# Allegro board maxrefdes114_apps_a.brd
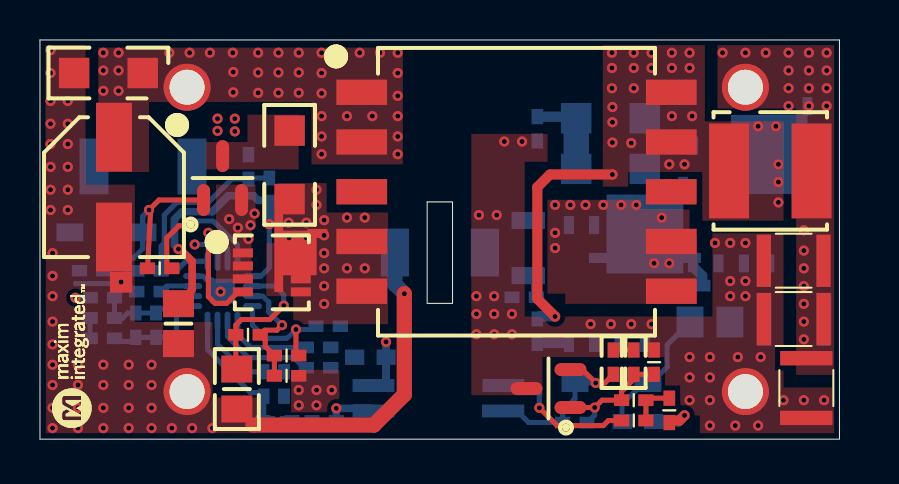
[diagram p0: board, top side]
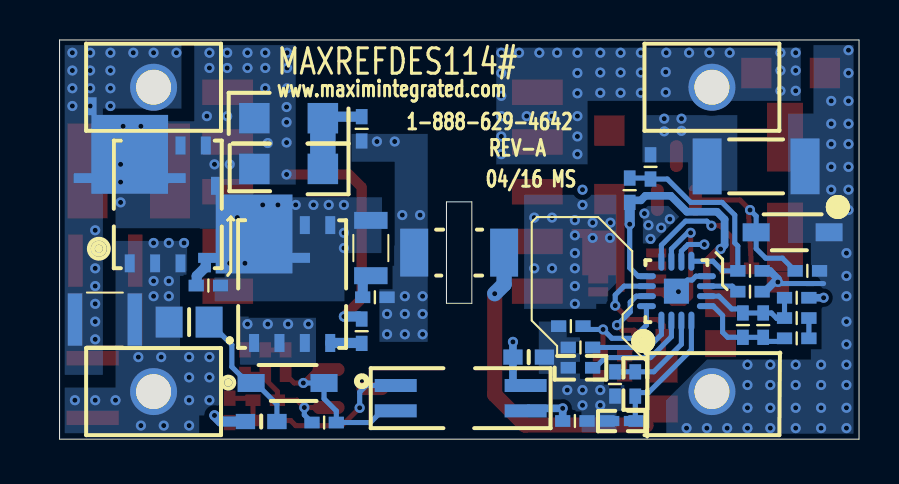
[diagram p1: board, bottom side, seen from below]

Outline 40 x 19.99 mm; copper layers: TOP, INTERNAL2, INTERNAL3, BOTTOM. Coordinates in mm from the lower left corner of the outline.
Outline path: 0,19.99 0,0 40,0 40,19.99 0,19.99 ; 19.38,11.88 19.38,6.8 20.65,6.8 20.65,11.88 19.38,11.88

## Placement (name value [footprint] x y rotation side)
C1  22UF  [CAPAE660X770M]  3.7 12.62 270 top
C2  8200PF  [0402]  3.12 6.06 180 bottom
C3  SHORT  [0402_SHORT]  11.88 0.91 180 bottom
C4  2.2UF  [1206]  3.42 18.33 180 top
C5  68PF  [0402]  4.8 5.71 270 bottom
C6  0.047UF  [0402]  5.46 7.39 180 bottom
C7  0.47UF  [0805]  9.85 2.51 90 top
C8  0.047UF  [0402]  5.99 8.55 180 top
C9  2.2UF  [CAPC2012X140M]  6.93 5.79 90 top
C11  1000PF  [0402]  5.46 8.43 0 bottom
C12  3900PF  [1206]  12.49 13.74 90 top
C13  1000PF  [CAPC4520X168M]  20.01 9.34 180 bottom
C14  OPEN  [0402]  24.23 7.11 180 bottom
C15  0.47UF  [0603]  16.53 4.11 0 bottom
C16  OPEN  [0402]  24.89 15.54 90 bottom
C17  22UF  [1210]  37.71 8.93 0 top
C18  2.2UF  [CAPC2012X140M]  33.52 5.86 180 bottom
C19  22UF  [1210]  38.35 2.56 90 top
C20  22UF  [1210]  37.74 5.99 0 bottom
C21  220PF  [0402]  26.77 0.83 180 bottom
C22  OPEN  [0402]  29.71 3.85 270 top
C23  22UF  [1210]  37.71 6.01 0 top
C24  0.01UF  [0402]  12.34 3.17 180 top
D3  1N4148W-7-F  [SOD3718X135M]  3.32 10.36 0 bottom
D7  1N4148W-7-F  [SOD3718X135M]  28.6 2.81 180 bottom
D8  TLV431BFTA  [SOT95P237X112-3M]  25.45 2.53 180 top
EV_KIT_BOX1  MEDIUM BOX  [EVKIT_PACKAGING]  -10.22 12.03 0 top
GNDO  FWJ-01-01-T-S  [SAMTEC_FWJ-01-01-X-X]  35.3 2.38 90 bottom
L1  4.7UH  [IND_XAL5030]  36.55 13.43 0 top
N1  SI7812DN-T1-GE3  [SON65P330X330X112-8M_POWERPAK_SINGLE]  11.6 8.35 0 top
N2  SIR412DP-T1-GE3  [SON127P615X500X112-8M_POWERPAK_SINGLE]  28.37 7.77 90 bottom
N3  SIR412DP-T1-GE3  [SON127P615X500X112-8M_POWERPAK_SINGLE]  34.59 11.75 90 bottom
NOREF  -  []  40 0 90 top
NOREF#2  -  []  20.01 11.88 0 top
NOREF#3  -  []  -12.32 19.73 0 top
NOREF#4  -  []  12.64 -7.3 0 top
NOREF#5  -  []  52.7 19.99 0 top
NOREF#6  -  []  52.7 0 0 top
NOREF#7  -  []  23.46 61.11 0 top
NOREF#8  -  []  156.33 16.55 0 top
NOREF#9  -  []  1.6 1.54 90 top
NOREF#10  -  []  0 19.99 0 top
P1  SI2337DS-T1-GE3  [SOT95P237X112-3M]  9.14 13.07 90 top
PGND  FWJ-01-01-T-S  [SAMTEC_FWJ-01-01-X-X]  7.36 2.38 90 bottom
Q4  ACPL-217-56AE  [SOIC127P700X242-4M]  19.93 2.05 180 bottom
R1  30K  [0402]  12.21 2.76 90 bottom
R2  OPEN  [0402]  13.94 3.58 0 bottom
R3  20K  [0402]  13.94 4.59 180 bottom
R4  OPEN  [0402]  11.2 2.76 90 bottom
R5  15K  [0402]  3.12 5.05 0 bottom
R6  24K  [0402]  14.42 5.66 180 bottom
R7  30K  [0402]  12.34 4.18 180 top
R9  47K  [0402]  5.81 5.71 270 bottom
R10  22K  [0402]  3.12 7.08 0 bottom
R11  680K  [0402]  10.41 5.23 0 top
R15  10K  [0402]  2.59 8.43 0 bottom
R16  6.49K  [0402]  11.48 12.47 270 bottom
R17  220  [0402]  10.43 13.63 90 bottom
R18  0.1  [RESC5025X175M]  5.15 13.66 0 bottom
R20  OPEN  [1206#2]  24.43 9.57 90 bottom
R23  10  [0402]  24.89 5.4 90 bottom
R24  10  [0402]  32.56 7.69 180 bottom
R25  OPEN  [1206]  28.54 16.07 0 bottom
R26  470  [0402]  14.22 0.91 0 bottom
R27  10K  [0603]  29.92 0.88 180 bottom
R30  OPEN  [0402]  28.7 3.85 270 top
R31  510  [0402]  29.71 0.93 0 top
R32  91K  [0402]  29.71 1.95 0 top
R33  30K  [0402]  30.73 3.85 270 top
R34  0  [0402]  31.49 1.44 270 top
R35  OPEN  [1206]  28.54 13.53 0 bottom
T1  TGSP-P148EP13LF  [EK_TGSP-P148EP13LF]  23.85 12.39 0 top
U1  MAX17599ATE+  [QFN50P300X300X80-17M]  9.14 7.41 90 bottom
VIN  FWJ-01-01-T-S  [SAMTEC_FWJ-01-01-X-X]  7.36 17.62 270 bottom
VOUT  FWJ-01-01-T-S  [SAMTEC_FWJ-01-01-X-X]  35.3 17.62 270 bottom

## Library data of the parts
C1 = CAP_POL: part number: CAP_POL_CASE_D8-CAPAE660X770M,22UF,20-0022U-59D
C2 = CAP_NP: alternate symbols: (0402_NOSILK); part number: CAP_NP_0402CAP-0402,8200PF,20-8200P-14
C3 = EVK_GENERIC_CAPACITORS: part number: EVK_GENERIC_CAPACITORS_0402CAP-0402_SHORT,N/A
C4 = CAP_NP: part number: CAP_NP_1206CAP-1206,2.2UF,20-002U2-72
C5 = CAP_NP: alternate symbols: 0402_NOSILK,CAPC1005X50L; part number: CAP_NP_0402CAP-0402,68PF,20-0068P-27
C6 C8 = CAP_NP: alternate symbols: (0402_NOSILK); part number: CAP_NP_0402CAP-0402,0.047UF,20-0U047-03
C7 = CAP_NP: alternate symbols: CAPC2012X145L,CAPC2012X140M; part number: CAP_NP_0805CAP-0805,0.47UF,20-00U47-04
C9 C18 = CAP_NP: part number: CAP_NP_0805CAP-CAPC2012X140M,2.2UF,20-002U2-89
C11 = CAP_NP: alternate symbols: 0402_NOSILK,CAPC1005X50L; part number: CAP_NP_0402CAP-0402,1000PF,20-1000P-14
C12 = CAP_NP: alternate symbols: CAPC3216X90L; part number: CAP_NP_1206CAP-1206,3900PF,20-3900P-09
C13 = CAP_NP: part number: CAP_NP_1808-CAPC4520X168M,1000PF,20-1000P-CA15
C14 C16 C22 = EVK_GENERIC_CAPACITORS: alternate symbols: 0402_NOSILK,CAPC1005X50L; part number: EVK_GENERIC_CAPACITORS_0402CAP-0402,N/A
C15 = CAP_NP: alternate symbols: (0603_NOSILK); part number: CAP_NP_0603CAP-0603,0.47UF,20-00U47-11
C17 C19 C20 C23 = CAP_NP: alternate symbols: CAPC3225X270L; part number: CAP_NP_1210CAP-1210,22UF,20-0022U-T7A
C21 = CAP_NP: alternate symbols: (0402_NOSILK); part number: CAP_NP_0402CAP-0402,220PF,20-0220P-E7
C24 = CAP_NP: alternate symbols: 0402_NOSILK,CAPC1005X50L; part number: CAP_NP_0402CAP-0402,0.01UF,20-00U01-B19
D3 D7 = DIO_SWITCH: part number: DIO_SWITCH_SOD-123-SOD3718X135M,1N4148W-7-F,30-1N4148W7F-00
D8 = TLV431: part number: TLV431_SOT23-SOT95P237X112-3M,TLV431BFTA,10-TLV431BFTA-U
EV_KIT_BOX1 = EV_KIT_BOX: part number: EV_KIT_BOX_ACCESSORY-N/A,MEDIUM BOX,EVKIT_PACKAGING
GNDO PGND VIN VOUT = HEADER_1P: part number: HEADER_1P_TH-SAMTEC_FWJ-01-01-X-X,FWJ-01-01-T-S,01-FWJ0101TS1P-19
L1 = INDUCT: part number: INDUCT_IND_XAL5030-IND_XAL5030,4.7UH,50-004U7-0IH
N1 = TRAN_NCH_8P: part number: TRAN_NCH_8P_POWERPAK-SINGLE-SON65P330X330X112-8M_POWERPAK_SINGLE,SI7812DN-T1-GE3,90-SI7812DN-33
N2 N3 = TRAN_NCH_8P: part number: TRAN_NCH_8P_POWERPAK-SINGLE-SON127P615X500X112-8M_POWERPAK_SINGLE,SIR412DP-T1-GE3,90-SIR412DP-23
P1 = TRAN_PCH_3P: part number: TRAN_PCH_3P_SOT-23-SOT95P237X112-3M,SI2337DS-T1-GE3,90-SI2337DS-16
Q4 = ACPL-217: part number: ACPL-217_SMD-SOIC127P700X242-4M,10-ACPL21756AE-S,ACPL-217-56AE
R1 R7 R33 = RES: alternate symbols: (0402_NOSILK,RESC1005X50L); part number: RES_0402RES-0402,30K,80-0030K-23G
R2 R4 R30 = EVK_GENERIC_RESISTORS: alternate symbols: 0402_NOSILK,RESC1005X50L; part number: EVK_GENERIC_RESISTORS_0402RES-0402,N/A
R3 = RES: alternate symbols: (0402_NOSILK,RESC1005X50L); part number: RES_0402RES-0402,20K,80-0020K-23
R5 = RES: alternate symbols: (0402_NOSILK,RESC1005X50L); part number: RES_0402RES-0402,15K,80-0015K-23
R6 = RES: alternate symbols: (0402_NOSILK,RESC1005X50L); part number: RES_0402RES-0402,24K,80-0024K-18
R9 = RES: alternate symbols: (0402_NOSILK,RESC1005X50L); part number: RES_0402RES-0402,47K,80-0047K-23
R10 = RES: alternate symbols: (0402_NOSILK,RESC1005X50L); part number: RES_0402RES-0402,22K,80-0022K-23
R11 = RES: alternate symbols: (0402_NOSILK,RESC1005X50L); part number: RES_0402RES-0402,680K,80-0680K-23
R15 = RES: alternate symbols: 0402_NOSILK,RESC1005X50L; part number: RES_0402RES-0402,10K,80-0010K-23
R16 = RES: alternate symbols: (0402_NOSILK,RESC1005X50L); part number: RES_0402RES-0402,6.49K,80-06K49-23
R17 = RES: alternate symbols: (0402_NOSILK,RESC1005X50L); part number: RES_0402RES-0402,220,80-0220R-23
R18 = RES: part number: RES_2010RES-RESC5025X175M,0.1,80-000R1-U25
R20 R25 R35 = EVK_GENERIC_RESISTORS: alternate symbols: RESC3116X60L; part number: EVK_GENERIC_RESISTORS_1206RES-1206,N/A
R23 R24 = RES: alternate symbols: 0402_NOSILK,RESC1005X50L; part number: RES_0402RES-0402,10,80-0010R-18
R26 = RES: alternate symbols: 0402_NOSILK,RESC1005X50L; part number: RES_0402RES-0402,470,80-0470R-AA23
R27 = RES: alternate symbols: (0603_NOSILK); part number: RES_0603RES-0603,10K,80-0010K-A9
R31 = RES: alternate symbols: (0402_NOSILK,RESC1005X50L); part number: RES_0402RES-0402,510,80-0510R-18
R32 = RES: alternate symbols: 0402_NOSILK,RESC1005X50L; part number: RES_0402RES-0402,91K,80-0091K-AA23
R34 = RES: alternate symbols: (0402_NOSILK,RESC1005X50L); part number: RES_0402RES-0402,0,80-0000R-26
T1 = EK_TGSP-P148EP13LF: part number: EK_TGSP-P148EP13LF_SMD-EK_TGSP-P148EP13LF,TGSP-P148EP13LF,N/A
U1 = MAX17599: part number: MAX17599_TQFN16-EP-QFN50P300X300X80-17M,MAX17599ATE+,10-MAX17599ATE-T

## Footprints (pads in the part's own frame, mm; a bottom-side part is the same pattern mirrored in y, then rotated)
0402
  rect 0.762x0.584 smd: 1(-0.61,0) 2(0.61,0)
0402_SHORT
  custom 0.146x0.146 smd: 1(-0.61,0) 2(0.61,0)
0603
  rect 0.965x0.762 smd: 1(-0.787,0) 2(0.787,0)
0805
  rect 1.35x1.55 smd: 1(-1,0) 2(1,0)
1206
  rect 1.524x1.524 smd: 1(-1.714,0) 2(1.714,0)
1206#2
  rect 0.85x1.67 smd: 1(-1.385,0) 2(1.385,0)
1210
  rect 0.72x2.62 smd: 1(-1.495,0) 2(1.495,0)
CAPAE660X770M
  rect 3.45x1.8 smd: 1(-2.5,0) 2(2.5,0)
CAPC2012X140M
  rect 1.35x1.55 smd: 1(-1,0) 2(1,0)
CAPC4520X168M
  rect 1.4x2.4 smd: 1(-2.25,0) 2(2.25,0)
EK_TGSP-P148EP13LF
  rect 2.54x1.27 smd: 1(-7.745,4.98) 2(-7.745,2.49) 3(-7.745,0) 4(-7.745,-2.49) 5(-7.745,-4.98) 6(7.745,-4.98) 7(7.745,-2.49) 8(7.745,0) 9(7.745,2.49) 10(7.745,4.98)
IND_XAL5030
  rect 2x4.75 smd: 1(-2.065,0) 2(2.065,0)
QFN50P300X300X80-17M
  oval 0.95x0.3 smd: 1(-1.5,0.75) 2(-1.5,0.25) 3(-1.5,-0.25) 4(-1.5,-0.75) 9(1.5,-0.75) 10(1.5,-0.25) 11(1.5,0.25) 12(1.5,0.75)
  oval 0.3x0.95 smd: 5(-0.75,-1.5) 6(-0.25,-1.5) 7(0.25,-1.5) 8(0.75,-1.5) 13(0.75,1.5) 14(0.25,1.5) 15(-0.25,1.5) 16(-0.75,1.5)
  rect 1.25x1.25 smd: 17(0,0)
RESC5025X175M
  rect 1.45x2.8 smd: 1(-2.45,0) 2(2.45,0)
SAMTEC_FWJ-01-01-X-X
  round 2.35 hole 1.75: 1(0,0)
SOD3718X135M
  rect 1.35x0.9 smd: A(1.825,0) C(-1.825,0)
SOIC127P700X242-4M
  rect 2.1x0.65 smd: 1(-3.25,0.635) 2(-3.25,-0.635) 3(3.25,-0.635) 4(3.25,0.635)
SON65P330X330X112-8M_POWERPAK_SINGLE
  rect 1x0.45 smd: 1(-1.45,0.975) 2(-1.45,0.325) 3(-1.45,-0.325) 4(-1.45,-0.975) 5(1.45,-0.975) 6(1.45,-0.325) 7(1.45,0.325)
  custom 0.663x0.663 smd: 8(1.45,0.975)
SON127P615X500X112-8M_POWERPAK_SINGLE
  rect 0.9x0.5 smd: 1(-2.95,1.905) 2(-2.95,0.635) 3(-2.95,-0.635) 4(-2.95,-1.905) 5(2.95,-1.905) 6(2.95,-0.635) 7(2.95,0.635)
  custom 1.209x1.209 smd: 8(2.95,1.905)
SOT95P237X112-3M
  oval 1.6x0.65 smd: 1(-1.1,0.95) 2(-1.1,-0.95) 3(1.1,0)

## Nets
GNDO: C13.1 C14.2 C16.1 C17.1 C18.1 C19.1 C20.1 C23.1 D8.3(A) GNDO.1 N2.1(S1) N2.2(S2) N2.3(S3) N3.1(S1) N3.2(S2) N3.3(S3) R33.1
PGND: C1.2(B) C4.2 C7.1 C9.1 C13.2 D3.C(K) PGND.1 R15.1 R18.1 U1.10(PGND)
SGND: C3.1 C6.2 C11.1 C15.1 C24.1 R1.1 R2.2 R3.1 R6.1 R26.1 U1.8(SGND) U1.17(EP)
UNNAMED_1_ACPL-217_I114_A: Q4.1(A) R31.1
UNNAMED_1_ACPL-217_I114_K: C21.2 D7.A D8.2(K) Q4.2(K) R30.2
UNNAMED_1_CAPNP_I10_1: C2.1 C5.1 R9.1 R10.2 U1.6(FB)
UNNAMED_1_CAPNP_I10_2: C5.2 R5.2 R9.2 U1.5(COMP)
UNNAMED_1_CAPNP_I15_1: C6.1 U1.7(SS)
UNNAMED_1_CAPNP_I43_2: C18.2 D7.C(K) R27.2
UNNAMED_1_CAPNP_I82_2: C1.1(A) C4.1 C7.2 R11.1 T1.1 T1.2 U1.14(VIN) VIN.1
UNNAMED_1_CAPNP_I84_2: C24.2 R7.2 R11.2 U1.15(EN/UVLO)
UNNAMED_1_CAPNP_I99_2: C2.2 R5.1
UNNAMED_1_CAPNP_I107_1: C12.1 N1.5(D1) N1.6(D2) N1.7(D3) N1.8(D4) T1.4 T1.5
UNNAMED_1_CAPNP_I107_2: C12.2 P1.3(D)
UNNAMED_1_CAPNP_I117_1: C21.1 C22.2 D8.1(REF) R32.1 R33.2
UNNAMED_1_CAPNP_I145_2: C11.2 R16.1 R17.1 U1.9(CS)
UNNAMED_1_CAPNP_I146_1: C8.1 U1.12(AUXDRV)
UNNAMED_1_DIOSWITCH_I147_A: C8.2 D3.A P1.1(G) R15.2
UNNAMED_1_EKTGSP-P148EP13LF_I162_10: L1.1 N3.5(D1) N3.6(D2) N3.7(D3) N3.8(D4) R23.2 R25.2 R35.2 T1.9 T1.10
UNNAMED_1_EVKGENERICCAPACITORS_I97_2: C3.2 R4.1 U1.4(DITHER/SYNC)
UNNAMED_1_EVKGENERICCAPACITORS_I116_1: C22.1 R30.1
UNNAMED_1_EVKGENERICCAPACITORS_I121_1: C14.1 R20.1
UNNAMED_1_EVKGENERICCAPACITORS_I124_2: C16.2 R25.1 R35.1
UNNAMED_1_EVKGENERICRESISTORS_I7_2: R1.2 R4.2 U1.3(RT)
UNNAMED_1_EVKGENERICRESISTORS_I140_1: R2.1 U1.2(SLOPE)
UNNAMED_1_MAX17599_I79_DT: R3.2 U1.1(DT)
UNNAMED_1_MAX17599_I79_NDRV: N1.4(G) U1.11(NDRV)
UNNAMED_1_RESSMD_I90_1: R6.2 R7.1 U1.16(OVI)
UNNAMED_1_RESSMD_I104_2: N1.1(S1) N1.2(S2) N1.3(S3) P1.2(S) R17.2 R18.2
UNNAMED_1_RESSMD_I118_1: N2.4(G) R23.1
UNNAMED_1_RESSMD_I119_1: N3.4(G) R24.1
UNNAMED_1_RESSMD_I119_2: N2.5(D1) N2.6(D2) N2.7(D3) N2.8(D4) R20.2 R24.2 T1.6 T1.7
UNNAMED_1_RESSMD_I156_1: R31.2 R32.2 R34.1
VDRV: C9.2 C15.2 Q4.4(C) R16.2 U1.13(VDRV)
VFB: Q4.3(E) R10.1 R26.2
VOUT: C17.2 C19.2 C20.2 C23.2 L1.2 R27.1 R34.2 VOUT.1

Pads without a net: T1 3 8

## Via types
v1: diameter 0.508, hole 0.254, TOP to BOTTOM, 226 vias

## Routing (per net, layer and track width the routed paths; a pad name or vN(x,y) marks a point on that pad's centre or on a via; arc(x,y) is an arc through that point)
GNDO:
  vias: v1(21.84,7.16) v1(21.84,6.27) v1(21.84,5.25) v1(21.97,11.22) v1(22.73,7.16) v1(22.73,6.27) v1(22.73,5.25) v1(22.85,11.22) v1(23.24,14.9) v1(23.62,6.27) v1(23.62,5.25) v1(24.12,14.9) v1(27.55,5.76) v1(28.57,5.76) v1(29.59,5.76) v1(30.6,5.76) v1(32.51,4.11) v1(32.51,3.09) v1(32.51,1.95) v1(33.52,4.11) v1(33.52,3.09) v1(33.52,1.95) v1(33.52,0.68) v1(33.78,9.82) v1(34.54,9.82) v1(34.54,7.92) v1(34.54,7.16) v1(34.79,0.68) v1(34.92,4.11) v1(35.3,9.82) v1(35.3,7.92) v1(35.3,7.16) v1(35.94,0.68) v1(36.06,4.11) v1(37.21,1.95) v1(38.22,1.95) v1(39.24,1.95)
PGND: length 18.2
  TOP w0.762: v1(18.23,7.28) 18.23,2.23 16.71,0.71 10.65,0.71
  BOTTOM w0.254: U1.10 8.89,9.42 8.7,9.61 8.69,9.61 8.56,9.75 v1(7.74,9.75) ; 1.77,7.79 2.64,7.79
  BOTTOM w0.762: C13.2 17.76,7.76 v1(18.23,7.28)
  vias: v1(0.53,19.48) v1(0.53,18.33) v1(0.53,16.94) v1(0.53,15.79) v1(0.53,14.78) v1(0.53,13.63) v1(0.53,12.49) v1(0.53,11.47) v1(0.63,9.32) v1(0.63,8.17) v1(0.63,7.16) v1(0.63,5.89) v1(0.63,4.74) v1(0.63,3.73) v1(0.63,2.71) v1(0.63,1.57) v1(0.63,0.55) v1(1.39,16.94) v1(1.39,15.79) v1(1.39,14.78) v1(1.39,13.63) v1(1.39,12.49) v1(1.39,11.47) v1(1.9,3.73) v1(1.9,2.71) v1(1.9,1.57) v1(1.9,0.55) v1(3.17,3.73) v1(3.17,2.71) v1(3.17,1.57) v1(3.17,0.55) v1(4.44,3.73) v1(4.44,2.71) v1(4.44,1.57) v1(4.44,0.55) v1(5.58,3.73) v1(5.58,2.71) v1(5.58,1.57) v1(5.58,0.55) v1(6.6,0.55) v1(7.61,0.55) v1(8.63,0.55)
SGND: length 5.7
  BOTTOM w0.254: U1.8 8.16,8.16 8.35,7.97 8.58,7.97 U1.17 ; v1(4.06,7.87) 4.01,7.87 3.93,7.79 2.28,7.79
  BOTTOM w0.381: C6.2 4.72,7.39 4.24,7.87 v1(4.06,7.87) 4.06,8.02 4.47,8.43 C11.1
  vias: v1(9.04,7.39) v1(12.95,2.46) v1(12.95,1.7) v1(13.84,2.46) v1(13.84,1.7) v1(14.6,2.46)
UNNAMED_1_ACPL-217_I114_A: length 7.3
  TOP w0.254: R31.1 28.44,0.93 28.19,0.68 25.88,0.68 v1(24.99,1.57)
  BOTTOM w0.254: Q4.1 24.66,2.69 24.99,2.36 v1(24.99,1.57)
UNNAMED_1_ACPL-217_I114_K: length 9.1
  TOP w0.254: R30.2 28.27,2.81 v1(27.81,2.81) 27.14,3.48 D8.2
  BOTTOM w0.254: Q4.2 23.87,1.42 24.46,0.83 C21.2 26.16,1.41 26.77,2.03 D7.A v1(27.81,2.81)
UNNAMED_1_CAPNP_I10_1: length 5.4
  BOTTOM w0.254: R10.2 C2.1 3.75,6.04 4.11,6.04 4.39,6.32 C5.1 R9.1 6.01,6.52 6.37,6.52 7.01,7.16 U1.6
UNNAMED_1_CAPNP_I10_2: length 5.2
  BOTTOM w0.254: U1.5 7.3,6.66 6.83,6.19 6.83,5.35 6.57,5.1 R9.2 C5.2 4.59,4.9 3.88,4.9 R5.2
UNNAMED_1_CAPNP_I15_1: length 1.7
  BOTTOM w0.254: C6.1 6.34,7.66 U1.7
UNNAMED_1_CAPNP_I43_2: length 6.6
  BOTTOM w0.254: C18.2 31.38,4.72 31.38,3.62 30.58,2.81 D7.C 30.2,2.81 29.13,1.75 R27.2
UNNAMED_1_CAPNP_I82_2: length 18.2
  TOP w0.254: v1(12.2,6.69) 11.5,5.99 10.08,5.99 9.8,5.71 R11.1 9.8,3.56 C7.2
  INTERNAL2 w0.381: 4.31,12.11 4.31,10.84 6.95,8.2 10.69,8.2 v1(12.2,6.69)
  BOTTOM w0.254: v1(12.2,6.69) 12.2,7.22 11.76,7.66 U1.14
  vias: v1(3.17,19.35) v1(3.17,18.46) v1(3.17,17.44) v1(3.93,19.35) v1(3.93,18.46) v1(3.93,17.44) v1(6.47,19.35) v1(7.49,19.35) v1(8.5,19.35) v1(9.65,19.35) v1(9.67,18.38) v1(9.67,17.37) v1(10.92,19.35) v1(10.92,18.36) v1(10.92,17.34) v1(11.93,19.35) v1(11.93,18.36) v1(11.93,17.34) v1(12.95,19.35) v1(12.95,18.36) v1(12.95,17.34) v1(14.09,19.35) v1(14.09,18.33) v1(14.09,17.32) v1(14.09,16.17) v1(14.09,15.16) v1(14.09,14.27) v1(15.11,19.35) v1(15.36,16.17) v1(16,19.35) v1(16.63,16.17) v1(17.01,19.35) v1(17.9,19.35) v1(17.9,18.33) v1(17.9,17.19) v1(17.9,16.17) v1(17.9,15.16) v1(17.9,14.27)
UNNAMED_1_CAPNP_I84_2: length 6
  TOP w0.254: C24.2 R7.2 11.27,4.64 11.27,4.97 R11.2 11.25,5.45 11.86,5.45 v1(12.11,5.71)
  BOTTOM w0.254: U1.15 11.15,7.16 11.45,6.86 11.45,6.37 v1(12.11,5.71)
UNNAMED_1_CAPNP_I99_2: length 1
  BOTTOM w0.254: C2.2 R5.1
UNNAMED_1_CAPNP_I107_1:
  vias: v1(12.44,10.84) v1(12.47,10.08) v1(13.33,10.84) v1(13.33,10.08) v1(13.84,12.49) v1(13.84,11.73) v1(14.22,10.97) v1(14.22,10.2) v1(14.22,9.32) v1(14.22,8.55) v1(14.22,7.66) v1(14.22,6.78) v1(15.36,11.09) v1(15.36,8.55) v1(16.25,11.09) v1(16.25,8.55)
UNNAMED_1_CAPNP_I117_1: length 6.2
  TOP w0.254: R33.2 C22.2 29.71,3 29.1,2.39 R32.1 28.12,1.95 v1(27.76,1.58) D8.1
  BOTTOM w0.254: C21.1 27.76,1.21 v1(27.76,1.58)
UNNAMED_1_CAPNP_I145_2: length 11.4
  BOTTOM w0.254: U1.9 7.31,8.91 6.83,8.43 C11.2 6.07,9.67 6.22,9.82 6.22,11.22 6.85,11.86 8.42,11.86 9.59,13.02 R17.1 10.49,13.07 R16.1
UNNAMED_1_CAPNP_I146_1: length 6.8
  TOP w0.254: v1(7.39,10.69) 6.95,10.69 6.34,10.08 6.34,8.81 6.6,8.55
  BOTTOM w0.254: U1.12 9.89,9.71 8.68,10.92 7.61,10.92 v1(7.39,10.69)
UNNAMED_1_DIOSWITCH_I147_A: length 10.4
  TOP w0.254: P1.1 5.96,11.97 v1(5.46,11.47) 5.53,11.39 C8.2
  BOTTOM w0.254: v1(5.46,11.47) 5.15,11.17 D3.A 5.15,9.54 4.67,9.06 3.83,9.06 R15.2
UNNAMED_1_EKTGSP-P148EP13LF_I162_10: length 11.8
  TOP w0.508: v1(25.78,6.14) 24.89,7.03 24.89,12.62 25.52,13.25 v1(28.65,13.25)
  BOTTOM w0.508: v1(25.78,6.14) 25.01,6.14 R23.2
  vias: v1(28.62,19.35) v1(28.62,18.59) v1(28.62,17.57) v1(28.65,16.63) v1(28.65,15.87) v1(28.65,14.85) v1(29.59,14.83) v1(29.71,19.35) v1(29.71,18.59) v1(29.71,17.57) v1(30.6,19.35) v1(30.6,18.59) v1(31.49,13.76) v1(31.62,19.35) v1(31.62,18.59) v1(31.62,16.17) v1(32.25,13.76) v1(32.51,19.35) v1(32.51,18.59) v1(32.63,16.17) v1(35.94,15.67) v1(36.82,15.67) v1(36.95,13.76) v1(36.95,12.87) v1(36.95,11.86)
UNNAMED_1_EVKGENERICCAPACITORS_I97_2: length 6.5
  BOTTOM w0.254: C3.2 11.2,0.98 R4.1 11.02,2.33 10.54,2.33 8.39,4.48 U1.4
UNNAMED_1_EVKGENERICCAPACITORS_I116_1: length 1
  TOP w0.254: R30.1 C22.1
UNNAMED_1_EVKGENERICCAPACITORS_I121_1: length 1.3
  BOTTOM w0.508: C14.1 24.84,7.89 24.54,8.18 R20.1
UNNAMED_1_EVKGENERICCAPACITORS_I124_2: length 4.5
  BOTTOM w0.508: C16.2 26.75,16.15 R25.1
  BOTTOM w1.27: R25.1 R35.1
UNNAMED_1_EVKGENERICRESISTORS_I7_2: length 5.1
  BOTTOM w0.254: U1.3 8.89,4.75 10.27,3.37 R4.2 R1.2
UNNAMED_1_EVKGENERICRESISTORS_I140_1: length 5.4
  BOTTOM w0.254: R2.1 13.21,3.58 12.7,4.08 10.43,4.08 9.39,5.13 U1.2
UNNAMED_1_MAX17599_I79_DT: length 4.4
  BOTTOM w0.254: R3.2 10.54,4.59 9.89,5.24 U1.1
UNNAMED_1_MAX17599_I79_NDRV: length 7.2
  TOP w0.254: v1(8.43,10.33) 8.43,7.13 8.76,6.8 9.34,6.8 9.92,7.38 N1.4
  BOTTOM w0.254: U1.11 9.39,9.52 8.58,10.33 v1(8.43,10.33)
UNNAMED_1_RESSMD_I90_1: length 6
  TOP w0.254: v1(12.81,5.49) 12.81,4.32 R7.1
  BOTTOM w0.254: U1.16 10.64,5.71 11.3,5.05 12.36,5.05 v1(12.81,5.49) 13.65,5.49 R6.2
UNNAMED_1_RESSMD_I104_2:
  vias: v1(8.88,16.05) v1(8.88,15.44) v1(9.47,11.02) v1(9.75,16.05) v1(9.75,15.41) v1(9.9,10.59) v1(10.43,10.03) v1(10.54,10.71) v1(10.74,11.3)
UNNAMED_1_RESSMD_I118_1: length 1.6
  BOTTOM w0.508: R23.1 24.89,4.82 N2.4
UNNAMED_1_RESSMD_I119_1: length 1.3
  BOTTOM w0.508: R24.1 33.14,7.72 33.14,8.17 32.68,8.63 N3.4
UNNAMED_1_RESSMD_I119_2:
  vias: v1(25.78,11.73) v1(25.78,10.33) v1(25.78,9.57) v1(26.54,11.73) v1(27.3,11.73) v1(28.19,11.73) v1(29.08,11.73) v1(29.84,11.73) v1(30.73,8.81) v1(31.11,11.09) v1(31.49,8.81)
UNNAMED_1_RESSMD_I156_1: length 2.2
  TOP w0.254: R34.1 30.42,2.05 R32.2 R31.2
VDRV: length 26.9
  TOP w0.381: C9.2 7.61,7.47 7.61,8.91 7.01,9.52 v1(6.93,9.52)
  INTERNAL2 w0.381: v1(17.32,4.87) 15.08,4.87 11.48,8.48 v1(11.48,10.76)
  BOTTOM w0.254: v1(11.48,10.76) 11.48,8.58 11.06,8.16 U1.13
  BOTTOM w0.381: v1(6.93,9.52) 6.73,9.72 6.73,11 7.11,11.39 8.62,11.39 9.42,12.19 10.69,12.19 10.92,11.96 11.37,11.96 R16.2 ; v1(17.32,4.87) C15.2 17.32,2.89 17.11,2.69 Q4.4
  BOTTOM w0.508: v1(11.48,10.76) R16.2
VFB: length 19.2
  INTERNAL2 w0.381: v1(14.83,1.54) 14.19,0.91 12.21,0.91 7.11,6.01 2.84,6.01 v1(1.77,7.08)
  BOTTOM w0.381: Q4.3 16.56,1.54 v1(14.83,1.54) R26.2 ; R10.1 v1(1.77,7.08)
VOUT: length 12.9
  TOP w0.508: R34.2 31.59,0.93 32,0.93 v1(32.25,1.19)
  INTERNAL2 w0.381: v1(32.25,1.19) 31.62,1.82 31.62,4.36 32.25,5 v1(38.22,5)
  BOTTOM w0.508: R27.1 31.95,0.88 v1(32.25,1.19)
  vias: v1(34.16,19.35) v1(35.3,19.35) v1(36.32,19.35) v1(37.46,19.35) v1(37.46,18.46) v1(37.46,17.57) v1(37.46,16.68) v1(38.22,10.46) v1(38.22,9.44) v1(38.22,8.55) v1(38.22,7.66) v1(38.22,6.78) v1(38.22,5.89) v1(38.48,19.35) v1(38.48,18.46) v1(38.48,17.57) v1(38.48,16.68) v1(39.36,19.35) v1(39.36,18.46) v1(39.36,17.57) v1(39.36,16.68)

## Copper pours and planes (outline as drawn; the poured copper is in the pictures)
GNDO on TOP: 33.01,0.3 33.01,1.19 31.26,1.19 31.26,4.11 25.14,4.11 25.14,2.2 21.58,2.2 21.58,15.28 25.39,15.28 25.39,13.89 24.25,13.89 24.25,6.14 33.65,6.14 33.65,10.31 37.21,10.31 37.21,2.84 39.75,2.84 39.75,0.3
GNDO on BOTTOM: 24,4.87 21.58,4.87 21.58,15.28 25.39,15.28 25.39,13.89 23.24,13.89 23.24,9.7 23.62,9.7 23.62,7.54 24,7.54
GNDO on BOTTOM: 27.17,3.73 27.17,6.14 30.98,6.14 30.98,3.73
GNDO on BOTTOM: 32,1.19 32,4.49 33.98,4.49 33.98,8.17 33.62,8.17 33.62,9.93 37.41,9.93 37.41,2.94 39.75,2.94 39.75,0.3 33.01,0.3 33.01,1.19
GNDO on INTERNAL2, INTERNAL3: 21.58,15.28 21.58,0.3 39.75,0.3 39.75,4.24 37.08,4.24 37.08,11.09 32.89,11.09 32.89,6.27 24.51,6.27 24.51,15.28
PGND on TOP (solid shape): 4.62,7.33 3.5,7.33 3.5,8.38 4.62,8.38
PGND on INTERNAL2 (solid shape): 4.82,7.28 3.17,7.28 3.17,8.43 4.82,8.43
PGND on TOP: 0.3,0.3 0.27,19.73 2.41,19.73 2.41,12.97 4.74,12.97 4.74,5.86 8.63,5.86 8.63,2.08 10.84,2.08 10.84,0.3
PGND on BOTTOM: 2.28,19.73 2.28,16.3 3.55,16.3 3.55,9.82 2.41,9.82 2.41,3.98 7.61,3.98 9.65,1.95 9.65,0.27 0.27,0.27 0.27,19.73
PGND on INTERNAL2: 1.77,19.73 1.77,11.35 3.3,11.35 5.58,9.06 5.58,5.76 7.11,5.76 9.14,3.73 9.14,0.27 0.27,0.27 0.27,19.73
PGND on INTERNAL3: 2.15,19.73 2.15,15.54 8.25,15.54 8.25,8.81 2.79,8.81 2.79,3.98 8,3.98 8,0.27 0.27,0.27 0.27,19.73
SGND on TOP: 12.57,3.47 12.57,1.31 14.98,1.31 14.98,3.47
SGND on BOTTOM: 11.65,2.71 11.65,0.35 13.89,0.35 13.89,1.39 15.34,1.39 15.34,3.17 16.02,3.17 16.02,5.96 14.63,5.96 14.63,5.1 13.94,5.1 13.94,3.02 12.49,3.02 12.49,2.71
SGND on INTERNAL3: 3.68,8.17 3.68,4.62 7.87,4.62 8.76,3.73 8.76,0.32 14.73,0.32 14.73,5 12.19,5 11.68,5.51 11.68,8.17
UNNAMED_1_CAPNP_I82_2 on TOP: 5.46,16.88 13.58,16.88 13.58,13.76 18.16,13.76 18.16,19.6 2.92,19.6 2.92,13.38 5.46,13.38
UNNAMED_1_CAPNP_I82_2 on BOTTOM: 13.58,16.94 13.58,13.76 18.16,13.76 18.16,19.6 2.92,19.6 2.92,16.94
UNNAMED_1_CAPNP_I82_2 on INTERNAL2, INTERNAL3: 18.16,13.76 13.58,13.76 13.58,16.94 6.98,16.94 6.98,11.98 2.15,11.98 2.15,19.73 18.16,19.73
UNNAMED_1_CAPNP_I107_1 on TOP: 17.42,5.76 12.67,5.76 12.67,7.16 11.32,7.16 11.32,9.82 11.91,9.82 11.91,12.82 14.35,12.82 14.35,11.35 17.42,11.35
UNNAMED_1_CAPNP_I107_1 on BOTTOM: 12.14,6.78 13.15,6.78 13.15,6.52 16.76,6.52 16.76,12.24 12.14,12.24
UNNAMED_1_CAPNP_I107_1 on INTERNAL2, INTERNAL3: 11.93,13.13 17.52,13.13 17.52,6.39 13.91,6.39 11.93,8.38
UNNAMED_1_CAPNP_I107_2 on TOP: 8.3,14.88 8.3,13.51 13.03,13.51 13.03,16.3 10.38,16.3 10.38,14.88
UNNAMED_1_EKTGSP-P148EP13LF_I162_10 on TOP: 28.16,19.73 28.16,12.64 29.43,12.64 29.43,13.38 33.14,13.38 33.14,10.84 37.33,10.84 37.33,16.17 33.27,16.17 33.27,19.73
UNNAMED_1_EKTGSP-P148EP13LF_I162_10 on BOTTOM: 28.19,12.74 32,12.74 32,10.53 37.59,10.53 37.59,16.2 33.5,16.2 33.5,19.73 28.19,19.73
UNNAMED_1_EKTGSP-P148EP13LF_I162_10 on INTERNAL2, INTERNAL3: 37.33,11.47 32.25,11.47 32.25,13 26.79,13 26.79,19.73 33.01,19.73 33.01,15.92 37.33,15.92
UNNAMED_1_RESSMD_I104_2 on TOP: 10.59,7.82 8.81,7.82 8.81,12.74 10.79,12.74 10.79,10.76 10.59,10.76
UNNAMED_1_RESSMD_I104_2 on BOTTOM: 8.5,11.68 10.82,11.68 10.82,9.8 8.5,9.8
UNNAMED_1_RESSMD_I104_2 on BOTTOM: 8.55,12.44 8.55,13.86 10.84,13.86 10.84,16.22 6.09,16.22 6.09,12.44
UNNAMED_1_RESSMD_I104_2 on INTERNAL2, INTERNAL3: 8.5,16.43 8.5,8.68 11.17,8.68 11.17,16.43
UNNAMED_1_RESSMD_I119_2 on TOP: 26.28,7.28 26.28,6.75 32.89,6.75 32.89,11.98 25.39,11.98 25.39,7.28
UNNAMED_1_RESSMD_I119_2 on BOTTOM: 23.9,11.14 23.9,9.32 25.75,9.32 25.75,6.9 32.25,6.9 32.25,8.1 31.74,8.1 31.74,12.11 23.87,12.11 23.87,11.14
UNNAMED_1_RESSMD_I119_2 on INTERNAL2, INTERNAL3: 25.14,12.36 31.62,12.36 31.62,10.59 32.25,10.59 32.25,6.9 25.14,6.9
VOUT on TOP, BOTTOM: 33.9,19.73 33.9,16.55 37.84,16.55 37.84,3.22 39.75,3.22 39.75,19.73
VOUT on INTERNAL2, INTERNAL3: 37.84,4.49 39.75,4.49 39.75,19.73 33.9,19.73 33.9,16.55 37.84,16.55

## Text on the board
Ref Des/Silkscreen Bottom: REV-A | 04/16 MS | 1-888-629-4642 | www.maximintegrated.com | MAXREFDES114#
DIMENSION: SLOT 0.05"(W)X0.200(H)" | NOTES: | FINISH: | TESTING: | MISCELLANEOUS: | TOOLING: | 16.  VENDOR LOGO & DATE CODE REQUIRED IN INK ON BOTTOM SIDE ONLY. DATE CODE FORMAT MUST BE YYWW ONLY | 17.  FINAL ELECTRICAL TEST TO BE PERFORMED USING PROVIDED IPC-D-356A NETLIST OR ODB++ FORMAT FILE. | 18.  A TIME DOMAIN REFLECTOMETER REPORT FOR EACH IMPEDANCE CONTROLLED LAYER AND A CERTIFICATE | 15.  CHECK ALL THAT APPLY | 14.  CHECK ALL THAT APPLY | 19. IF PRESENT, ALL BLIND/BURIED VIAS WITH AN ASPECT RATIO <1:1 TO BE PLATED SHUT WITH COPPER WHEN | 20.  FOR ALL DRILL INFORMATION REFER TO DRILL CHART. | 21.  FINISHED SURFACE CONTACTS AND FILLED VIAS TO BE FREE OF ANY PITS. SCRATCHES PROBE MARKS | 23.  PEMNUT | 13.  DRILL SIZES ARE FINISHED HOLE SIZES. ALL HOLES SHALL BE LOCATED WITHIN .005 DTP. | 22.  THIEVING: | 9.  ALL TRACES FILLETED OPTION TO ENHANCE RELIABILITY AT PAD JUNCTIONS | 10.  LAYER TO LAYER REGISTRATIONS SHALL BE WITHIN .003 INCHES. | MATERIAL: | 11.  PLATING SPECIFICATION: | 24.  INTENTIONAL SHORTS PRESENT. REFER TO SHORT REPORT IN FAB PACKAGE. | 12.  CHECK ALL THAT APPLY | 8.  IF STATED IN THE LAMINATION DIAGRAM, THE DIELECTRIC THICKNESS OF ANY | 1.  DIMENSIONS ARE IN INCHES (EXCEPT WHERE NOTED). | 3.  THE PCB SHALL BE FABRICATED TO IPC-6012, TYPE X, CLASS 2. | 4.  BOARD MATERIAL & CONSTRUCTION SHALL MEET THE REQUIREMENTS OF UL796 | 5.  OVERALL BOARD THICKNESS REFER TO LAMINATION DIAGRAM. TOLERANCE APPLIES | 6.  BOW & TWIST NOT TO EXCEED 0.0075 IN. (0.75%) PER LINEAR INCH. | 7.  PHOTO ETCH CIRCUITRY PER ENCLOSED GERBER RS274X OR ODB++ FORMAT FILE. | 2.  BOARD MATERIAL: | ( )  FINISH CONDUCTOR SURFACES: IMMERSION GOLD, 2-5 MICRO INCHES OVER | ( )  STARTING COPPER WEIGHT FOR OUTER LAYERS TO BE (1 OZ), THE FINISH COPPER WEIGHT IS (1 OZ). | ( )  STARTING COPPER WEIGHT FOR OUTER LAYERS TO BE (1 OZ), THE FINISH COPPER WEIGHT IS (2 OZ). | (X)  STARTING COPPER WEIGHT FOR OUTER LAYERS TO BE (2 OZ), THE FINISH COPPER WEIGHT IS (2 OZ)MINIMUM. | ( )  OTHER ________________________ | (X)  FINISH CONDUCTOR SURFACES: IMMERSION GOLD, 3-8 MICRO INCHES OVER | ( )  FINGERS TO BE GOLD PLATED. | ( )  LEAD FREE AND RoHS COMPLIANT PLATING. | ( )  GREEN SOLDERMASK OVER BARE COPPER/BARE GOLD (BOTH SIDES) WITH LIQUID PHOTO IMAGEABLE INK (LPI) | (x )  GREEN TAIYO PSR-4000 | () OTHER _____________________ | ( )  ELECTRODEPOSITED HARD GOLD PLATE, TYPE 1 (99.7% MIN GOLD), GRADE C | (X)  APPLY SILKSCREEN USING A NON-CONDUCTIVE, WHITE EPOXY | THE STARTING WEIGHT CAN BE (0.5 OZ) AS LONG AS THE FINISH COPPER WEIGHT IS (2 OZ). | THE STARTING WEIGHT CAN BE (<2 OZ) AS LONG AS THE FINISH COPPER WEIGHT IS (2 OZ). | MINIMUM BARREL PLATING OF .001 IN. PLATED HOLES SHALL NOT BE ROUGH OR IRREGULAR | SO AS TO HINDER PROPER SOLDER WICKING. | USED AS VIA-IN PAD OR AS A STACKED VIA. BLIND/BURIED VIAS WITH AN ASPECT RATIO >1:1 TO BE FILLED | WITH NON-CONDUCTIVE EPOXY. UNLESS OTHERWISE SPECIFIED. | ( )  NON-CONDUCTIVE EPOXY. FILL AND CAP ALL 0.XXXX INCH DRILLED VIAS. | ( )  SILVER. FILL AND CAP ALL 0.XXXX INCH DRILLED VIAS. | (REQUIRED UNLESS OTHERWISE SPECIFIED IN QUOTE) | THE PCB SHALL HAVE A VERIFICATION STAMP. | OF COMPLIANCE SHALL BE PROVIDED BY VENDOR AT TIME OF SHIPMENT. | OR OTHER DEFORMITIES THAT COULD EFFECT THE APPERANCE AND PERFORMACE OF THE CONTACT | SURFACE. CONTACTS ARE TO BE AS FLAT AS POSSIBLE. NOT TO EXCEED +/- 0.001" OF FLATNESS. | ( )  SUPPLIER MAY ADD THIEVING TO COMPENSATE FOR LOW COPPER DENSITY AREAS ON THIS DESIGN. | WHERE SPACING PERMITS. | LEGEND TO LEGEND +/- 0.007 INCHES | (X)  SUPPLIER MAY NOT ADD THIEVING TO COMPENSATE FOR LOW COPPER DENSITY AREAS ON THIS DESIGN. | ( )  PEMNUTS TO BE INSTALLED BY SUPPLIER. | ( )  PEMNUTS NOT TO BE INSTALLED BY SUPPLIER. | (X)  NOT APPLICABLE | CONTROLLED IMPEDANCE LAYER IS FOR REFERENCE ONLY. FINAL ACCEPTANCE | SHALL BE DETERMINED BY THESE LAYERS HAVING A CHARACTERISTIC | IMPEDANCE OF +/-10% OHMS AS STATED IN THE LAMINATION DIAGRAM. THE | VENDOR CAN MAKE ADJUSTMENTS AS LONG AS THE STATED IMPEDANCE AND | OVERALL BOARD THICKNESS IS MAINTAINED. ANY ADJUSTMENT MADE TO TRACE | WIDTH OR SPACING MUST HAVE PRIOR WRITTEN APPROVAL FROM MAXIM. | ( )  FILLETED | (X)  NOT FILLETED | (X)  ISOLA 370HR OR EQUIVALENT | ( )  NELCO-4000-13 | ( )  MEGTRON 6 | ( )  ROGERS 4350B | ( )  ROGERS 4003C | ( )  ISOLA-FR408HR OR EQUIVALENT | WORKMANSHIP SHALL CONFORM TO IPC-A-600, CLASS 2, CURRENT REVISIONS. | WITH FLAMMABILITY RATING OF 94V-O. | AFTER ALL LAMINATION AND PLATING PROCESSES. IT IS TO BE MEASURED FROM | TOP PCB METAL TO BOTTOM PCB METAL UNLESS OTHERWISE SPECIFIED. | BOW & TWIST SHOULD BE MEASURED PER IPC-TM-650, METHOD 2.4.22. | DRILL LOCATION AND SIZE CONTROLLED BY EXCELLON CNC DRILL FILE. | FOR OUTER LAYERS WHERE SPACING PREVENTS THE USE OF (1 OZ) AS A STARTING WEIGHT, | FOR OUTER LAYERS WHERE SPACING PREVENTS THE USE OF (2 OZ) AS A STARTING WEIGHT, | UNLESS OTHERWISE SPECIFIED | FOR OUTER LAYERS WHERE SPACING PREVENTS THE USE OF (1 OZ) AS A STARTING WEIGHT | THE STARTING WEIGHT CAN BE (0.5 OZ) AS LONG AS THE FINISH COPPER WEIGHT IS (1 OZ) | (KNOOP HARDNESS 130-200), CLASS 1 (50-100 MICRO INCHES THICK) IN ACCORDANCE WITH MIL-G-45204C. | GENERAL SURFACING REQUIREMENTS MUST MEET ANSI/IPC-A-600(CURRENT REV) SECTION 4.0, | CLASS 3 (50-100 MICROINCHES THICK) OVER ELECTRODEPOSITED NICKEL PLATE | IN ACCORDANCE WITH ANSI/IPC-A-600D, SECTION 4.0, CLASS 3 (200-600 MICROINCHES THICK). | 100 MICRO INCHES MINIMUM OF ELECTROLESS NICKEL. | 118-236 MICRO INCHES MINIMUM OF ELECTROLESS NICKEL. | PER ARTWORK. | BASED INK PER ARTWORK. | (USE CHECKED ITEMS FOR MATERIAL) | (USE CHECKED ITEMS FOR PLATING) | (USE CHECKED ITEMS FOR TOOLING) | UNLESS OTHERWISE SPECIFIED: | P1 | A | VINCENT LI | INITIAL RELEASE | PRODUCTION RELEASE | 04/15/16 | VL | 02/03/16 | MAXREFDES114_APPS
User.25: FIGURE | SIZE | 10.0 | 68.9 | TOLERANCE | +3.0/-8.0 | +3.0/-3.0 | PLATED | ALL UNITS ARE IN MILS | QTY | 226 | 4 | NOTES | DRILL CHART: TOP to BOTTOM
